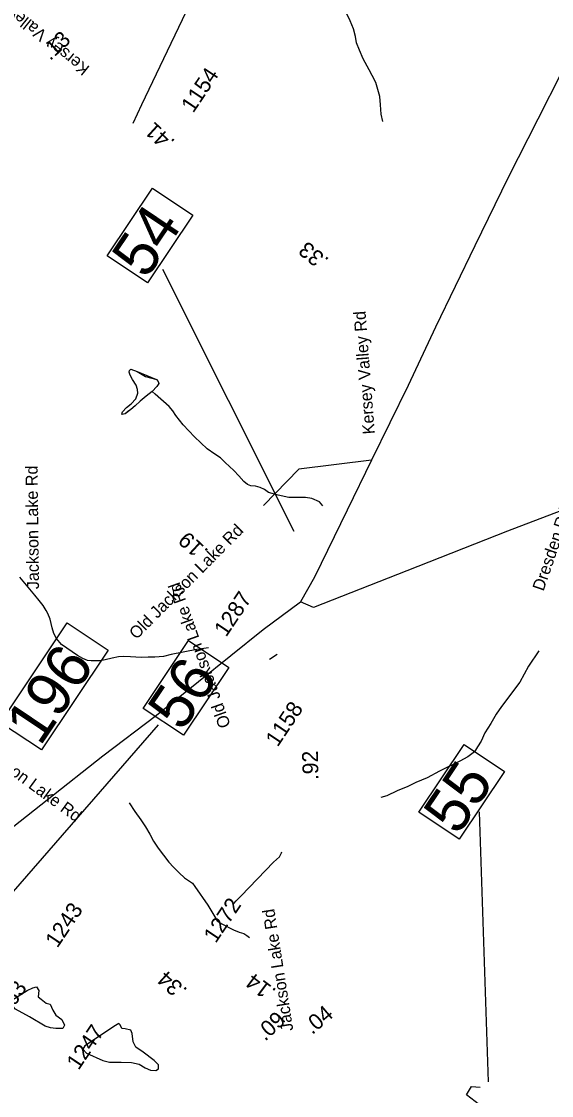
# Model space of a CAD drawing. Extents: x 1716282 to 1717158, y 799307 to 801078.
# Drawn here: x 1716976.7 to 1717037.3, y 800850 to 800972.8 of the extents above; entities that cross this region are included whole.
import ezdxf

# ---------------------------------------------------------------- set-up
doc = ezdxf.new("R2010")
doc.units = 0
for name, color, linetype in [('Exist Hydrographic Misc Water Feature', 7, 'Continuous'), ('Exist Hydrographic Pond Under 1500 Sq Ft', 7, 'Continuous'), ('Exist Road Non-System Type 51', 7, 'Continuous'), ('Exist Road Non-System Type 51 Label', 7, 'Continuous'), ('Exist Road Secondary Mileage Hundredths English Label', 7, 'Continuous'), ('Exist Road Secondary Mileage Tenths English Label', 7, 'Continuous'), ('Exist Road Secondary Structure Private Number Label', 7, 'Continuous'), ('Exist Road Secondary Structure Standard Bridge Number Label', 7, 'Continuous'), ('Exist Road Secondary Type 51 Label', 7, 'Continuous'), ('Exist Road Secondary Type 51 Number Label', 7, 'Continuous'), ('Exist Utilities Electrical Transmission Line', 7, 'Continuous')]:
    doc.layers.add(name, color=color, linetype=linetype)

msp = doc.modelspace()

# ---------------------------------------------------------------- linework, layer by layer
at = {"layer": 'Exist Hydrographic Misc Water Feature'}
msp.add_line((1717005.11, 800899.91), (1717005.97, 800900.49), dxfattribs=at)
for points in [[(1717018.06, 800961.39), (1717017.86, 800962.23), (1717017.79, 800963.3), (1717017.72, 800964.23), (1717017.25, 800965.85), (1717016.84, 800966.65), (1717016.47, 800967.29), (1717015.79, 800968.56), (1717015.38, 800969.55), (1717015.04, 800970.38), (1717014.92, 800971.09), (1717014.69, 800971.99), (1717014.32, 800972.88), (1717013.81, 800973.93), (1717013.05, 800975.96), (1717012.78, 800977.01), (1717012.44, 800977.74), (1717012, 800978.49), (1717011.64, 800979.24), (1717010.95, 800980.9), (1717010.88, 800981.48)], [(1716991.67, 800930.52), (1716990.98, 800929.98), (1716990.32, 800929.41), (1716989.75, 800928.89), (1716989.24, 800928.46), (1716988.84, 800928.17), (1716988.58, 800927.96), (1716988.42, 800927.93), (1716988.26, 800927.9), (1716988.21, 800927.93), (1716988.27, 800928.17), (1716988.76, 800928.68), (1716989.29, 800929.09), (1716989.8, 800929.69), (1716990.04, 800930.34), (1716990.02, 800930.73), (1716989.84, 800931.24), (1716989.43, 800931.87), (1716989.17, 800932.37), (1716989.04, 800932.74), (1716989.07, 800932.93), (1716989.25, 800933.05), (1716989.97, 800932.81), (1716990.93, 800932.22), (1716991.64, 800932.02), (1716992.17, 800931.87), (1716992.38, 800931.66), (1716992.44, 800931.44), (1716992.23, 800931.09), (1716991.67, 800930.52)], [(1716991.67, 800930.52), (1716990.98, 800929.98), (1716990.32, 800929.41), (1716989.75, 800928.89), (1716989.24, 800928.46), (1716988.58, 800927.96), (1716988.42, 800927.93), (1716988.26, 800927.9), (1716988.21, 800927.93), (1716988.27, 800928.17), (1716988.76, 800928.68), (1716989.29, 800929.09), (1716989.8, 800929.69), (1716990.04, 800930.34), (1716990.02, 800930.73), (1716989.84, 800931.24), (1716989.43, 800931.87), (1716989.17, 800932.37), (1716989.04, 800932.74), (1716989.07, 800932.93), (1716989.25, 800933.05), (1716989.97, 800932.81), (1716992.17, 800931.87), (1716992.38, 800931.66), (1716992.44, 800931.44), (1716992.23, 800931.09), (1716991.67, 800930.52)], [(1717011.19, 800917.44), (1717010.79, 800917.88), (1717009.94, 800918.29), (1717009.19, 800918.38), (1717008.19, 800918.39), (1717007.29, 800918.41), (1717006.08, 800918.65), (1717004.99, 800918.96), (1717004.53, 800919.31), (1717004.03, 800919.55), (1717003.48, 800919.68), (1717002.95, 800919.73), (1717002.57, 800919.88), (1717002.17, 800920.22), (1717001.59, 800920.87), (1717001.03, 800921.49), (1717000.04, 800922.41), (1716999.49, 800922.93), (1716998.86, 800923.36), (1716997.98, 800923.97), (1716996.53, 800925.34), (1716995.23, 800926.69), (1716994.38, 800927.76), (1716994.05, 800928.3), (1716993.62, 800928.8), (1716992.02, 800930.21), (1716991.67, 800930.52)], [(1716998.13, 800901.2), (1716996.78, 800901.03), (1716993.85, 800900.44), (1716992.97, 800900.23), (1716992, 800900.15), (1716991.22, 800900.13), (1716990.43, 800900.11), (1716989.21, 800900.17), (1716988.4, 800900.23), (1716987.83, 800900.16), (1716987.1, 800900.02), (1716986.3, 800899.83), (1716985.68, 800899.73), (1716985.1, 800899.71), (1716984.7, 800899.7), (1716984.29, 800899.77), (1716983.75, 800900), (1716983.14, 800900.34), (1716982.52, 800900.73), (1716981.3, 800901.6), (1716980.73, 800902.27), (1716980.42, 800902.84), (1716980.23, 800903.49), (1716980.02, 800904.47), (1716979.76, 800905.11), (1716979.56, 800905.49), (1716979.2, 800906.05), (1716978.77, 800906.6), (1716978.28, 800907.21), (1716976.55, 800909.27)], [(1716989.05, 800883.48), (1716989.71, 800882.5), (1716990.39, 800881.55), (1716990.92, 800880.73), (1716991.4, 800879.88), (1716991.84, 800879.08), (1716992.36, 800878.31), (1716993.58, 800876.7), (1716994.13, 800876.11), (1716994.75, 800875.48), (1716995.38, 800874.91), (1716995.95, 800874.52), (1716996.29, 800874.29), (1716996.57, 800873.92), (1716998.04, 800871.76), (1716998.97, 800870.24), (1716999.12, 800870), (1716999.65, 800869.64), (1717000.97, 800868.95), (1717001.63, 800868.68), (1717002.15, 800868.52), (1717002.51, 800868.32), (1717002.8, 800868.08)], [(1717026.79, 800836.33), (1717027.72, 800838.49), (1717030.6, 800842.94), (1717030.25, 800845.68), (1717029.11, 800848.95), (1717027.6, 800850.11), (1717028.19, 800851.05), (1717029.17, 800850.95)]]:
    msp.add_lwpolyline(points, dxfattribs=at)
at = {"layer": 'Exist Hydrographic Pond Under 1500 Sq Ft'}
for points in [[(1716979.44, 800857.95), (1716977.65, 800859.01), (1716976.07, 800859.87), (1716975.54, 800860.49), (1716975.62, 800860.91), (1716977.38, 800862.03), (1716978.05, 800862.32), (1716978.47, 800862.45), (1716978.71, 800862.01), (1716978.65, 800861.31), (1716978.99, 800861.02), (1716979.57, 800860.57), (1716980.03, 800860.46), (1716980.33, 800859.79), (1716980.68, 800859.21), (1716981.35, 800858.7), (1716981.67, 800858.07), (1716981.47, 800857.67), (1716980.66, 800857.67), (1716980.04, 800857.75), (1716979.44, 800857.95)], [(1716987.5, 800858.02), (1716984, 800855.71), (1716983.75, 800855.33), (1716984.17, 800854.85), (1716986.03, 800854.01), (1716986.8, 800853.84), (1716988.13, 800853.82), (1716989.31, 800853.77), (1716990.2, 800853.58), (1716990.88, 800853.19), (1716991.5, 800852.91), (1716992.08, 800852.87), (1716992.41, 800853.05), (1716992.39, 800853.53), (1716991.89, 800854), (1716990.65, 800854.97), (1716989.81, 800855.53), (1716989.49, 800856.15), (1716989.38, 800857.1), (1716989.23, 800857.47), (1716988.59, 800857.63), (1716988.22, 800857.68), (1716988.02, 800858.08), (1716987.86, 800858.25), (1716987.5, 800858.02)]]:
    msp.add_lwpolyline(points, dxfattribs=at)
at = {"layer": 'Exist Road Non-System Type 51'}
for points in [[(1717022.18, 800988.3), (1717018.59, 800985.59), (1717017.36, 800984.84), (1717014.47, 800983.47), (1717013.53, 800983.12), (1717008.9, 800981.05), (1717006.58, 800980.34), (1717004.84, 800980.14), (1716998.68, 800979.01), (1716998.2, 800978.83), (1716997.95, 800978.65), (1716997.64, 800978.29), (1716990.45, 800963.3), (1716989.48, 800961.14)], [(1717035.87, 800900.86), (1717034.7, 800899.12), (1717033.71, 800897.26), (1717031.61, 800894.5), (1717030.99, 800893.62), (1717030.39, 800892.55), (1717029.7, 800891.5), (1717029.3, 800890.53), (1717028.87, 800889.88), (1717028.54, 800889.3), (1717027.77, 800888.75), (1717026.85, 800888.23), (1717024.54, 800887.09), (1717023.12, 800886.32), (1717021.81, 800885.82), (1717020.92, 800885.35), (1717019.7, 800884.86), (1717018.5, 800884.28), (1717017.8, 800884.09)], [(1717001.02, 800871.96), (1717001.3, 800872.29), (1717001.86, 800872.86), (1717005.55, 800876.7), (1717006.23, 800877.32), (1717006.48, 800877.76), (1717006.5, 800877.89)]]:
    msp.add_lwpolyline(points, dxfattribs=at)
at = {"layer": 'Exist Road Secondary Structure Private Number Label'}
msp.add_lwpolyline([(1716974.35, 800892.64), (1716981.98, 800904.05), (1716986.64, 800900.93), (1716979.01, 800889.53)], close=True, dxfattribs=at)
at = {"layer": 'Exist Road Secondary Structure Standard Bridge Number Label'}
for p, q in [((1717007.93, 800914.52), (1716992.91, 800944.48)), ((1716964.81, 800860.8), (1716992.42, 800892.39)), ((1717030.13, 800851.59), (1717029.09, 800882.45))]:
    msp.add_line(p, q, dxfattribs=at)
for points in [[(1716986.53, 800946.02), (1716991.72, 800953.78), (1716996.33, 800950.69), (1716991.14, 800942.93)], [(1716990.64, 800894.28), (1716995.84, 800902.05), (1717000.45, 800898.96), (1716995.25, 800891.2)], [(1717022.16, 800882.4), (1717027.36, 800890.16), (1717031.97, 800887.08), (1717026.77, 800879.32)]]:
    msp.add_lwpolyline(points, close=True, dxfattribs=at)
at = {"layer": 'Exist Utilities Electrical Transmission Line'}
for points in [[(1717048.36, 800990.05), (1717048.52, 800987.62), (1717044.45, 800979.06), (1717038.49, 800966.99), (1717035.76, 800961.65), (1717032.38, 800954.97), (1717028.55, 800947.16), (1717024.08, 800937.87), (1717020.93, 800931.21), (1717016.76, 800922.67)], [(1717113.38, 800946.53), (1717106.69, 800943.87), (1717098.42, 800940.66), (1717094.79, 800939.11), (1717087.49, 800936.29), (1717077.91, 800932.55), (1717070.7, 800929.7), (1717064.61, 800927.25), (1717055.5, 800923.57), (1717046.79, 800920.13), (1717040.78, 800917.8), (1717032.3, 800914.53), (1717020.79, 800909.99), (1717010.13, 800905.8), (1717008.63, 800906.48)], [(1717016.76, 800922.67), (1717008.43, 800921.65), (1717004.42, 800917.48)], [(1717016.76, 800922.67), (1717013.98, 800916.95), (1717010.25, 800909.3), (1717008.63, 800906.48)], [(1716975.86, 800880.8), (1716979.66, 800883.81), (1716986.03, 800888.86), (1716992.19, 800893.51), (1716996.97, 800897.37), (1717004.38, 800903.28), (1717008.63, 800906.48)]]:
    msp.add_lwpolyline(points, dxfattribs=at)

# ---------------------------------------------------------------- texts
at = {"layer": 'Exist Road Non-System Type 51 Label'}
for rotation, p in [(45.2182, (1716989.88, 800902.09)), (109.6728, (1717000.67, 800892.32))]:
    msp.add_text('Old Jackson Lake Rd', height=1.3775, rotation=rotation, dxfattribs=at).set_placement(p)
at = {"layer": 'Exist Road Secondary Mileage Hundredths English Label'}
for s, height, rotation, p in [('.13', 1.813, 42.8047, (1716980.02, 800968.27)), ('.41', 1.813, 137.5133, (1716994.39, 800959.15)), ('.09', 1.813, 42.8226, (1717004.59, 800856.16)), ('.04', 1.812, 40.5079, (1717009.97, 800856.91))]:
    msp.add_text(s, height=height, rotation=rotation, dxfattribs=at).set_placement(p)
at = {"layer": 'Exist Road Secondary Mileage Tenths English Label'}
for s, height, rotation, p in [('.33', 1.812, 140.5851, (1717011.99, 800945.64)), ('.19', 1.813, 137.2193, (1716998.21, 800912.33)), ('.92', 1.813, 91.4728, (1717010.7, 800886.09)), ('.34', 1.812, 137.6689, (1716995.8, 800862.14)), ('.14', 1.812, 143.1087, (1717005.97, 800862.08))]:
    msp.add_text(s, height=height, rotation=rotation, dxfattribs=at).set_placement(p)
at = {"layer": 'Exist Road Secondary Structure Private Number Label'}
msp.add_text('196', height=5.075, rotation=56.2051, dxfattribs=at).set_placement((1716978.87, 800889.84))
at = {"layer": 'Exist Road Secondary Structure Standard Bridge Number Label'}
for s, p in [('54', (1716991, 800943.24)), ('56', (1716995.11, 800891.51)), ('55', (1717026.63, 800879.63))]:
    msp.add_text(s, height=5.075, rotation=56.2051, dxfattribs=at).set_placement(p)
at = {"layer": 'Exist Road Secondary Type 51 Label'}
for s, height, rotation, p in [('Kersey Valley Rd', 1.3775, 141.2373, (1716984.63, 800967.6)), ('Kersey Valley Rd', 1.3775, 94.4036, (1717017.14, 800925.67)), ('Jackson Lake Rd', 1.3775, 90.7212, (1716978.75, 800907.92)), ('Dresden Rd', 1.377, 71.123, (1717036.41, 800907.61)), ('Jackson Lake Rd', 1.3775, 323.8288, (1716971.56, 800889.56)), ('Jackson Lake Rd', 1.3775, 98.9245, (1717007.82, 800857.48))]:
    msp.add_text(s, height=height, rotation=rotation, dxfattribs=at).set_placement(p)
at = {"layer": 'Exist Road Secondary Type 51 Number Label'}
for s, p in [('1154', (1716996.37, 800962.27)), ('1287', (1717000.14, 800902.36)), ('1158', (1717006.02, 800889.79)), ('1272', (1716998.94, 800867.34)), ('1243', (1716980.84, 800866.8)), ('1263', (1716974.44, 800857.88)), ('1247', (1716983.27, 800852.83))]:
    msp.add_text(s, height=1.812, rotation=56.2051, dxfattribs=at).set_placement(p)

doc.saveas('drawing.dxf')
